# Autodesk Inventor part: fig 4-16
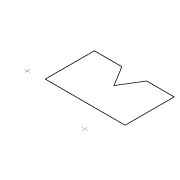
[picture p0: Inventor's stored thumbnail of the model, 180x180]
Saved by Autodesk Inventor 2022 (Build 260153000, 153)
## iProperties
Created: 2005-02
Part Number: fig 4-16
Document SubType Name: Modeling
Designer: CADCIM
Manufacturer: Standard
Standards Organization: Custom
Density: 1 g/cm^3
Material: Generic
Appearance: Default
Author: CADCIM
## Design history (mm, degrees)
sketch "Sketch1"
  geometry: L1 (-25.19, 27.524)-(-25.19, 5.557); L2 (-25.19, 5.557)-(10.567, 5.557); L3 (10.567, 5.557)-(10.567, 27.524); L4 (10.567, 27.524)-(-1.76, 27.524); L5 (-1.76, 27.524)-(-7.312, 18.449); L6 (-7.312, 18.449)-(-12.863, 27.524); L7 (-12.863, 27.524)-(-25.19, 27.524); 2 further points
  constraints: 14 end point, 3 equal length, 3 parallel, 1 perpendicular, 1 vertical, 1 other
